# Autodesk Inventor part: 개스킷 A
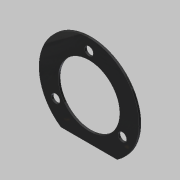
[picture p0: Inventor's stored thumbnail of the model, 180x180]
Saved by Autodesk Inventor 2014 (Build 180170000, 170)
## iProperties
Created: 2020-04
Part Number: 개스킷 A
Material: 고무
Document SubType Name: Modeling
Designer: mduedu
Density: 0.93 g/cm^3
Appearance: 고무 - 검은색 - 버전 1.1
Mass: 1.09963 g
Surface Area: 26.6928 cm^2
Volume: 1.18239 cm^3
Author: mduedu
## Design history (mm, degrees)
sketch "스케치1"
  geometry: C1 r 26 at (0, 0); 1 further point
  constraints: 1 centre point, 1 coincident
  dimensions: "d0" = 52 diameter of C1
extrude "돌출1" new body sketch "스케치1" distance "d1" = 1; taper "d2" = 0 deg
sketch "스케치2"
  geometry: L1 (-14.62, -21.5)-(14.62, -21.5); A1 r 26 centre (0, 0) between (-14.62, -21.5) and (14.62, -21.5) reference; 1 further point
  constraints: 2 end point, 2 point on circle, 1 horizontal
  dimensions: "d3" = 21.5 distance from line of L1 point (0, 0)
extrude "돌출2" cut sketch "스케치2" stored distance "d4" = 1; taper "d5" = 0 deg
sketch "스케치3" dims "d6" = 40
  geometry: 3 further points
  constraints: 2 vertical alignment, 1 coincident, 2 other
hole "구멍1" sketch "스케치3" at (0, 20) diameter "d7" = 4.5; stored, may be unused: countersink angle "d11" = 90 deg, drill point angle "d13" = 118 deg; dims "d8" = 6, "d9" = 4, "d10" = 2, "d12" = 8
sketch "스케치4"
  geometry: C1 r 16 at (0, 0); 1 further point
  constraints: 1 centre point, 1 coincident
  dimensions: "d17" = 32 diameter of C1
extrude "돌출3" cut sketch "스케치4" stored distance "d18" = 1; taper "d19" = 0 deg
node "솔리드1"
pattern_circular "원형 패턴1" dims angle "d15" = 360 deg
node "투영된 루프1"
